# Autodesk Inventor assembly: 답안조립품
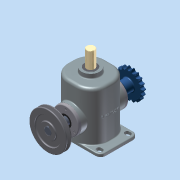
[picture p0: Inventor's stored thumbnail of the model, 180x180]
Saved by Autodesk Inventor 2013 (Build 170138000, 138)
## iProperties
Created: 2014-12
Part Number: 답안조립품
Document SubType Name: Assembly
Designer: 교육생
Mass: 8322.52 g
Surface Area: 4222.88 cm^2
Volume: 1869.1 cm^3
Density: 4.4527 g/cm^3
Author: 교육생
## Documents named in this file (15)
- C:\Documents and Settings\교육생\바탕 화면\341208V1034\답안조립품.iam
- C:\Documents and Settings\교육생\바탕 화면\341208V1034\본체.ipt
- C:\Documents and Settings\교육생\바탕 화면\341208V1034\V-벨트풀리.ipt
- C:\Documents and Settings\교육생\바탕 화면\341208V1034\편심축.ipt
- C:\Documents and Settings\교육생\바탕 화면\341208V1034\체인 스프로킷.ipt
- C:\Documents and Settings\교육생\바탕 화면\341208V1034\커버.ipt
- C:\Documents and Settings\교육생\바탕 화면\341208V1034\슬라이드.ipt
- C:\Documents and Settings\교육생\바탕 화면\341208V1034\오일실.ipt
- C:\Documents and Settings\교육생\바탕 화면\341208V1034\베어링 6205.ipt
- C:\Documents and Settings\교육생\바탕 화면\341208V1034\부시.ipt
- C:\Documents and Settings\교육생\바탕 화면\341208V1034\키 8x8.ipt
- C:\Documents and Settings\교육생\바탕 화면\341208V1034\M4x0.5.ipt
- C:\Documents and Settings\교육생\바탕 화면\341208V1034\멈춤링.ipt
- C:\Documents and Settings\교육생\바탕 화면\341208V1034\멈춤나사 M5x0.5.ipt
- C:\Documents and Settings\교육생\바탕 화면\341208V1034\7가변스프링.ipt
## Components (9 placed, 4 different names)
1. V-벨트풀리:1 — 구동부
2. 5-체인 스프로킷:1
3. 7가변스프링:1
4. M4x0.5:4
5. M4x0.5:5
6. M4x0.5:6
7. M4x0.5:1
8. M4x0.5:2
9. M4x0.5:3
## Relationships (1: Angle 1)
- 구동부 [Angle]: V-벨트풀리:1
